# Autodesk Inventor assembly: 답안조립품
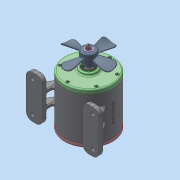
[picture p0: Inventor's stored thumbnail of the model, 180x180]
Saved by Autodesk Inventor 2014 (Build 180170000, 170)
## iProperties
Created: 2024-02
Part Number: 답안조립품
Document SubType Name: Assembly
Designer: dg
Mass: 3108.48 g
Surface Area: 2333.46 cm^2
Volume: 963.013 cm^3
Density: 3.22787 g/cm^3
Author: dg
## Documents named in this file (20)
- C:\Users\dg\Desktop\640204V1010\답안조립품.iam
- C:\Users\dg\Desktop\640204V1010\본체.ipt
- C:\Users\dg\Desktop\640204V1010\뒷커버.ipt
- C:\Users\dg\Desktop\640204V1010\베어링 608.ipt
- C:\Users\dg\Desktop\640204V1010\오일 실 8 22 7.ipt
- C:\Users\dg\Desktop\640204V1010\육각 소켓 머리 볼트 M4 x 12.ipt
- C:\Users\dg\Desktop\640204V1010\메인 기어 축.ipt
- C:\Users\dg\Desktop\640204V1010\서브 기어 축.ipt
- C:\Users\dg\Desktop\640204V1010\베어링 6903.ipt
- C:\Users\dg\Desktop\640204V1010\앞커버.ipt
- C:\Users\dg\Desktop\640204V1010\오일 실 17 30 8.ipt
- C:\Users\dg\Desktop\640204V1010\키 5 x 5 x 24.ipt
- C:\Users\dg\Desktop\640204V1010\팬날개.ipt
- 팬날개.ipt
- C:\Users\dg\Desktop\640204V1010\스프링 와셔 M6.ipt
- C:\Users\dg\Desktop\640204V1010\육각 소켓 머리 볼트 M6 x 12.ipt
- C:\Users\dg\Desktop\640204V1010\부시.ipt
- C:\Users\dg\Desktop\640204V1010\슬라이더.ipt
- C:\Users\dg\Desktop\640204V1010\가변스프링.ipt
- C:\Users\dg\Desktop\640204V1010\앤드 캡.ipt
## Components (1 placed, 1 different names)
1. 가변스프링:1
